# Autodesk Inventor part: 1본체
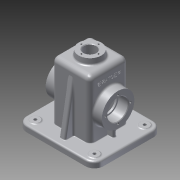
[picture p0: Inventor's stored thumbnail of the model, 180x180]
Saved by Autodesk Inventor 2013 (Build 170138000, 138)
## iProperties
Created: 2016-01
Part Number: 1본체
Material: 알루미늄 6061
Document SubType Name: Modeling
Designer: Administrator
Density: 2.71 g/cm^3
Mass: 874.944 g
Surface Area: 893.712 cm^2
Volume: 322.858 cm^3
Author: Administrator
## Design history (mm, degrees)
sketch "스케치1"
  geometry: L1 (-65, 57.5)-(65, 57.5); L2 (65, 57.5)-(65, -57.5); L3 (65, -57.5)-(-65, -57.5); L4 (-65, -57.5)-(-65, 57.5); L5 (-65, 57.5)-(65, -57.5); L6 (65, 57.5)-(-65, -57.5); 1 further point
  constraints: 12 end point, 2 midpoint, 2 parallel, 1 horizontal, 1 perpendicular
  dimensions: "d0" = 130 distance of L1.start L1.end; "d2" = 115 distance of L1.end L2.end
extrude "돌출1" new body sketch "스케치1" distance "d3" = 10; taper "d4" = 0 deg
fillet "모깎기1" dims "d5" = 15
sketch "스케치3"
  geometry: L1 (32.5, -32.5)-(-32.5, -32.5); L2 (-32.5, -32.5)-(-32.5, 32.5); L3 (-32.5, 32.5)-(32.5, 32.5); L4 (32.5, 32.5)-(32.5, -32.5); L5 (32.5, -32.5)-(-32.5, 32.5); L6 (-32.5, -32.5)-(32.5, 32.5); L7 (50, 57.5)-(-50, 57.5) reference; 1 further point
  constraints: 12 end point, 2 midpoint, 2 parallel, 1 horizontal, 1 perpendicular
  dimensions: "d134" = 65 distance of L2.end L3.end; "d136" = 25 distance between parallel lines of L3 L7
extrude "돌출2" join sketch "스케치3" distance "d16" = 98; taper "d17" = 0 deg
sketch "스케치4"
  geometry: C1 r 20 at (0, 0); 1 further point
  constraints: 1 centre point, 1 coincident
  dimensions: "d18" = 40 diameter of C1
extrude "돌출3" join sketch "스케치4" distance "d19" = 10; taper "d20" = 0 deg
sketch "스케치7"
  geometry: C1 r 7.5 at (-50, 42.5); A1 r 15 centre (-50, 42.5) between (-50, 57.5) and (-65, 42.5) reference; 1 further point
  constraints: 1 centre point, 1 coincident
  dimensions: "d33" = 15 diameter of C1
extrude "돌출6" join sketch "스케치7" distance "d34" = 1; taper "d35" = 0 deg
sketch "스케치9"
  geometry: L1 (-50, 52.5)-(50, 52.5); L2 (60, 42.5)-(60, -42.5); L3 (50, -52.5)-(-50, -52.5); L4 (-60, -42.5)-(-60, 42.5); L5 (-60, 52.5)-(60, -52.5); L6 (60, 52.5)-(-60, -52.5); A1 r 10 centre (-50, 42.5) between (-50, 52.5) and (-60, 42.5); A2 r 10 centre (50, 42.5) between (60, 42.5) and (50, 52.5); A3 r 10 centre (50, -42.5) between (50, -52.5) and (60, -42.5); A4 r 10 centre (-50, -42.5) between (-60, -42.5) and (-50, -52.5); 1 further point
  constraints: 12 end point, 8 point on circle, 8 point on line, 8 tangent, 4 centre point, 3 equal radius, 2 midpoint, 2 parallel, 1 horizontal, 1 perpendicular
  dimensions: "d38" = 120 distance of L5.start L6.start; "d39" = 105 distance of L6.start L5.end; "d40" = 10 radius of A1
extrude "돌출7" join sketch "스케치9" distance "d41" = 2; taper "d42" = 0 deg
sketch "스케치10"
  geometry: 2 further points
  dimensions: "d43" = 42.5 vertical distance of point (0, 0) point (50, 42.5); "d44" = 50 horizontal distance of point (50, 42.5) point (0, 0)
hole "구멍2" sketch "스케치10" at (50, 42.5) diameter "d45" = 5; stored, may be unused: countersink angle "d49" = 90 deg, drill point angle "d51" = 118 deg; dims "d46" = 6, "d47" = 4, "d48" = 2, "d50" = 8
sketch "스케치17"
  geometry: L1 (0, 65)-(0, 0) reference; L2 (10, 75)-(10, -10) reference; L3 (0, 0)-(-98, 0) reference; L4 (-98, 0)-(-98, 65) reference; L5 (-98, 65)-(0, 65) reference; L6 (0, 0)-(0, 65) reference; L7 (0, -25)-(0, 0) reference; L8 (10, -25)-(0, -25) reference; L9 (10, -20)-(10, -25) reference; L10 (12, -20)-(10, -20) reference; L11 (12, 85)-(12, -20) reference; L12 (10, 85)-(12, 85) reference; L13 (10, 90)-(10, 85) reference; L14 (0, 90)-(10, 90) reference; L15 (0, 65)-(0, 90) reference; L16 (0, 0)-(-98, 0) reference; L17 (-98, 0)-(-98, 65) reference; L18 (-98, 65)-(0, 65) reference; L19 (0, 0)-(0, 65) reference; L20 (0, -25)-(0, 0) reference; L21 (10, -25)-(0, -25) reference; L22 (10, -20)-(10, -25) reference; L23 (12, -20)-(10, -20) reference; L24 (12, 85)-(12, -20) reference; L25 (10, 85)-(12, 85) reference; L26 (10, 90)-(10, 85) reference; L27 (0, 90)-(10, 90) reference; L28 (0, 65)-(0, 90) reference; L29 (0, 0)-(-98, 0) reference; L30 (-98, 0)-(-98, 65) reference; L31 (-98, 65)-(0, 65) reference; L32 (0, 0)-(0, 65) reference; L33 (0, -25)-(0, 0) reference; L34 (10, -25)-(0, -25) reference; L35 (10, -20)-(10, -25) reference; L36 (12, -20)-(10, -20) reference; L37 (12, 85)-(12, -20) reference; L38 (10, 85)-(12, 85) reference; L39 (10, 90)-(10, 85) reference; L40 (0, 90)-(10, 90) reference; L41 (0, 65)-(0, 90) reference; L42 (0, 0)-(-98, 0) reference; L43 (-98, 0)-(-98, 65) reference; L44 (-98, 65)-(0, 65) reference; L45 (0, 0)-(0, 65) reference; L46 (0, -25)-(0, 0) reference; L47 (10, -25)-(0, -25) reference; L48 (10, -20)-(10, -25) reference; L49 (12, -20)-(10, -20) reference; L50 (12, 85)-(12, -20) reference; L51 (10, 85)-(12, 85) reference; L52 (10, 90)-(10, 85) reference; L53 (0, 90)-(10, 90) reference; L54 (0, 65)-(0, 90) reference; L55 (0, -10)-(0, 75) reference; C1 r 27.5 at (-43, 32.5); 2 further points
  constraints: 1 centre point, 1 horizontal alignment, 1 midpoint
  dimensions: "d127" = 55 diameter of C1; "d129" = 55 distance from line of L11 C1.centre
extrude "돌출11" join sketch "스케치17" distance "d130" = 15; taper "d132" = 0 deg; dims "d131" = 80, "d133" = 0
sketch "스케치18"
  geometry: L1 (-32.5, 10)-(-32.5, 108) reference; L2 (-32.5, 108)-(-20, 108) reference; L3 (-20, 108)-(-20, 118) reference; L4 (-20, 118)-(20, 118) reference; L5 (20, 118)-(20, 108) reference; L6 (20, 108)-(32.5, 108) reference; L7 (32.5, 108)-(32.5, 10) reference; L8 (32.5, 10)-(57.5, 10) reference; L9 (57.5, 10)-(57.5, 0) reference; L10 (57.5, 0)-(52.5, 0) reference; L11 (52.5, 0)-(52.5, -2) reference; L12 (52.5, -2)-(-52.5, -2) reference; L13 (-52.5, -2)-(-52.5, 0) reference; L14 (-52.5, 0)-(-57.5, 0) reference; L15 (-57.5, 0)-(-57.5, 10) reference; L16 (-57.5, 10)-(-32.5, 10) reference; L17 (-27.5, -2)-(27.5, -2); L18 (27.5, -2)-(27.5, 103); L19 (27.5, 103)-(-27.5, 103); L20 (-27.5, 103)-(-27.5, -2); 2 further points
  constraints: 8 end point, 2 parallel, 1 horizontal, 1 midpoint, 1 perpendicular, 1 point on line, 1 vertical alignment
  dimensions: "d137" = 105 distance of L17.end L18.end; "d140" = 5 distance between parallel lines of L7 L18
extrude "돌출12" cut sketch "스케치18" stored distance "d141" = 55; taper "d142" = 0 deg
fillet "모깎기8" dims "d143" = 8
fillet "모깎기9" dims "d144" = 8
feature "면 기울기3" dims angle "d145" = 5 deg
hole "구멍7" diameter "d148" = 30; stored, may be unused: countersink angle "d152" = 90 deg, drill point angle "d154" = 118 deg; dims "d146" = 10, "d147" = 10, "d149" = 8, "d150" = 35, "d151" = 17, "d153" = 35
hole "구멍8" diameter "d157" = 35; stored, may be unused: countersink angle "d161" = 90 deg, drill point angle "d163" = 0 deg; dims "d155" = 10, "d156" = 10, "d158" = 8, "d159" = 35, "d160" = 17, "d162" = 17
hole "구멍9" diameter "d166" = 21; stored, may be unused: countersink angle "d170" = 90 deg, drill point angle "d172" = 0 deg; dims "d164" = 10, "d165" = 10, "d167" = 8, "d168" = 35, "d169" = 17, "d171" = 17
sketch "스케치19"
  geometry: C1 r 17.5 at (0, 0) reference; 2 further points
  constraints: 1 horizontal alignment
  dimensions: "d173" = 21 distance of point (-21, 0) C1.centre
hole "구멍10" sketch "스케치19" at (-21, 0) diameter "d174" = 3.242; stored, may be unused: countersink angle "d178" = 90 deg, drill point angle "d180" = 118 deg; dims "d175" = 8, "d176" = 35, "d177" = 17, "d179" = 10
sketch "스케치20"
  geometry: C1 r 10.5 at (0, 0) reference; 1 further point
  constraints: 1 horizontal alignment
  dimensions: "d184" = 14.5 distance of C1.centre point (14.5, 0)
hole "구멍11" sketch "스케치20" at (14.5, 0) diameter "d185" = 2.459; stored, may be unused: countersink angle "d189" = 90 deg, drill point angle "d191" = 118 deg; dims "d186" = 7, "d187" = 35, "d188" = 17, "d190" = 9
sketch "스케치21"
  geometry: L1 (24.5, -32.5)-(-24.5, -32.5) reference; L2 (-50, -57.5)-(50, -57.5) reference; L3 (-5, -32.5)-(5, -32.5); L4 (5, -32.5)-(5, -47.5); L5 (5, -47.5)-(-5, -47.5); L6 (-5, -47.5)-(-5, -32.5); 2 further points
  constraints: 8 end point, 2 parallel, 1 horizontal, 1 midpoint, 1 perpendicular, 1 point on line, 1 vertical alignment
  dimensions: "d195" = 10 distance of L4.end L5.end; "d198" = 10 distance between parallel lines of L5 L2
extrude "돌출13" join sketch "스케치21" distance "d199" = 105; taper "d200" = 0 deg
feature "면 기울기4" dims angle "d201" = 10 deg
feature "면 기울기5" dims angle "d202" = 10 deg
sketch "스케치22"
  geometry: L1 (32.5, 24.5)-(32.5, -24.5) reference; L2 (32.5, 3)-(42.5, 3); L3 (42.5, 3)-(42.5, -3); L4 (42.5, -3)-(32.5, -3); L5 (32.5, -3)-(32.5, 3); 2 further points
  constraints: 8 end point, 2 parallel, 1 horizontal, 1 horizontal alignment, 1 midpoint, 1 perpendicular, 1 point on line
  dimensions: "d203" = 10 distance of L3.end L4.end; "d206" = 6 distance of L2.end L3.end
extrude "돌출14" join sketch "스케치22" stored distance "d207" = 0; taper "d208" = 0 deg
fillet "모깎기10" dims "d209" = 3
fillet "모깎기11" dims "d210" = 3
fillet "모깎기12" dims "d211" = 1
fillet "모깎기13" dims "d212" = 3
fillet "모깎기14" dims "d213" = 3
fillet "모깎기18" dims "d217" = 0.3
chamfer "모따기1" distance "d218" = 1; stored, may be unused: second distance "d219" = 2, angle "d220" = 45 deg
node "작업 평면3"
sketch "스케치23"
  geometry: L1 (43.625, 18)-(5.375, 18) reference; 3 further points
  constraints: 1 midpoint, 1 vertical alignment, 1 other
  dimensions: "d221" = 27 distance from line of L1 point (24.5, -9)
feature "엠보싱2" sketch "스케치23" dims "d134" = 65, "d136" = 25, "d222" = 0.5, "d223" = 0
fillet "모깎기19" dims "d224" = 3
fillet "모깎기20" dims "d225" = 3
sketch "스케치11"
  geometry: L1 (27.5, -2)-(-27.5, -2); L2 (-27.5, -2)-(-27.5, 103); L3 (-27.5, 103)-(27.5, 103); L4 (27.5, 103)-(27.5, -2); L5 (65, 10)-(65, 0) reference; L6 (65, 0)-(60, 0) reference; L7 (60, 0)-(60, -2) reference; L8 (60, -2)-(-60, -2) reference; L9 (-60, -2)-(-60, 0) reference; L10 (-60, 0)-(-65, 0) reference; L11 (-65, 0)-(-65, 10) reference; L12 (-65, 10)-(-40, 10) reference; L13 (-40, 10)-(-40, 108) reference; L14 (-40, 108)-(-20, 108) reference; L15 (-20, 108)-(-20, 118) reference; L16 (-20, 118)-(20, 118) reference; L17 (20, 118)-(20, 108) reference; L18 (20, 108)-(40, 108) reference; L19 (40, 108)-(40, 10) reference; L20 (40, 10)-(65, 10) reference; 3 further points
  constraints: 8 end point, 2 coincident, 2 midpoint, 2 parallel, 1 horizontal, 1 perpendicular
  dimensions: "d52" = 55 distance of L2.end L3.end; "d54" = 105 distance of L3.end L1.start
extrude "돌출8" cut sketch "스케치11" stored distance "d55" = 55; taper "d56" = 0 deg
sketch "스케치13"
  geometry: L1 (32.5, -32.5)-(-32.5, -32.5) reference; L2 (-3, -32.5)-(3, -32.5); L3 (3, -32.5)-(3, -42.5); L4 (3, -42.5)-(-3, -42.5); L5 (-3, -42.5)-(-3, -32.5); 2 further points
  constraints: 8 end point, 2 parallel, 1 horizontal, 1 midpoint, 1 perpendicular, 1 point on line, 1 vertical alignment
  dimensions: "d59" = 10 distance of L2.end L3.end; "d61" = 6 distance of L3.end L4.end
extrude "돌출9" join sketch "스케치13" stored distance "d62" = 10; taper "d63" = 0 deg
hole "구멍3" diameter "d66" = 30; stored, may be unused: countersink angle "d70" = 90 deg, drill point angle "d72" = 118 deg; dims "d64" = 10, "d65" = 10, "d67" = 6, "d68" = 35, "d69" = 17, "d71" = 8
hole "구멍4" diameter "d75" = 35; stored, may be unused: countersink angle "d79" = 90 deg, drill point angle "d81" = 0 deg; dims "d76" = 6, "d77" = 35, "d78" = 17, "d80" = 17, "d93" = 10, "d94" = 10
hole "구멍5" diameter "d84" = 21; stored, may be unused: countersink angle "d88" = 90 deg, drill point angle "d90" = 0 deg; dims "d85" = 6, "d86" = 35, "d87" = 17, "d89" = 21, "d91" = 10, "d92" = 10
sketch "스케치14"
  geometry: C1 r 17.5 at (0, 0) reference; 2 further points
  constraints: 1 vertical alignment
  dimensions: "d95" = 21 distance of point (0, 21) C1.centre
hole "구멍6" sketch "스케치14" at (0, 21) diameter "d96" = 3.242; stored, may be unused: countersink angle "d100" = 90 deg, drill point angle "d102" = 118 deg; dims "d97" = 8, "d98" = 35, "d99" = 17, "d101" = 10
fillet "모깎기2" dims "d106" = 8
fillet "모깎기3" dims "d107" = 8
node "작업 평면2"
sketch "스케치15"
  geometry: L1 (-28, -102)-(-28, -100) reference; L2 (-28, -100)-(-33, -100) reference; L3 (-33, -100)-(-33, -90) reference; L4 (-33, -90)-(0, -90) reference; L5 (0, -90)-(0, 0) reference; L6 (64, -90)-(64, 0) reference; L7 (64, -90)-(97, -90) reference; L8 (97, -90)-(97, -100) reference; L9 (97, -100)-(92, -100) reference; L10 (92, -100)-(92, -102) reference; L11 (92, -102)-(-28, -102) reference; L12 (0, -90)-(64, -90) reference; L13 (0, 0)-(64, 0) reference; L14 (52, 18)-(12, 18) reference; L15 (-8, 0)-(-8, -90) reference; C1 r 17.5 at (32, -45) reference; C2 r 27.5 at (32, -45) reference; 2 further points
  constraints: 1 vertical alignment, 1 other
  dimensions: "d108" = 27 distance from line of point (32, -9) L14
feature "엠보싱1" sketch "스케치15" dims "d109" = 0.5, "d110" = 0, "d134" = 65, "d136" = 25
fillet "모깎기4" dims "d111" = 3
feature "면 기울기1" dims angle "d112" = 5 deg
fillet "모깎기5" dims "d113" = 3
fillet "모깎기6" dims "d114" = 3
sketch "스케치16"
  geometry: L1 (40, 24.5)-(40, -24.5) reference; L2 (40, 5)-(55, 5); L3 (55, 5)-(55, -5); L4 (55, -5)-(40, -5); L5 (40, -5)-(40, 5); L6 (65, -42.5)-(65, 42.5) reference; 3 further points
  constraints: 8 end point, 2 horizontal alignment, 2 midpoint, 2 parallel, 1 horizontal, 1 perpendicular, 1 point on line
  dimensions: "d119" = 10 distance of L2.end L3.end; "d121" = 10 distance between parallel lines of L3 L6
extrude "돌출10" join sketch "스케치16" distance "d122" = 105; taper "d123" = 0 deg
feature "면 기울기2" dims angle "d124" = 10 deg
fillet "모깎기7" dims "d125" = 3
node "솔리드1"
mirror "대칭1"
mirror "대칭2"
pattern_circular "원형 패턴2" dims angle "d182" = 360 deg
mirror "대칭5"
pattern_circular "원형 패턴3" dims angle "d193" = 360 deg
mirror "대칭6"
mirror "대칭7"
pattern_circular "원형 패턴1" dims angle "d104" = 360 deg
mirror "대칭3"
mirror "대칭4"
node "절단 모서리 투영2"
node "절단 모서리 투영4"
node "절단 모서리 투영5"
node "절단 모서리 투영6"
node "절단 모서리 투영7"
node "절단 모서리 투영8"
node "절단 모서리 투영9"
